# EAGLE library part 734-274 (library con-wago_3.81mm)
Serie 734, Stiftleiste (für Leiterplatten) Einlötstift abgewinkelt 1 x 1 mm / Series 734, Male header (for PCBs) Angled solder pin 1 x 1 mm Polzahl / Pole No.: 14 Rastermaß / Pitch: 3.81 mm Bemessungsspannung / Rated Voltage: 160 V Nennstrom / Nominal Current: 10 A Lötstiftlänge: / Solder Pin Length: 3.8 mm Farbe / Color: orange / orange Stand: 01.01.2012. Die jeweils aktuellen Daten zu diesem Artikel finden Sie in unserem Produktkatalog, den Sie unter www.wago.com einsehen können. As of: 01/01/2012. Please find the newest data for this article in our product catalogue, which can be viewed under www.wago.com.
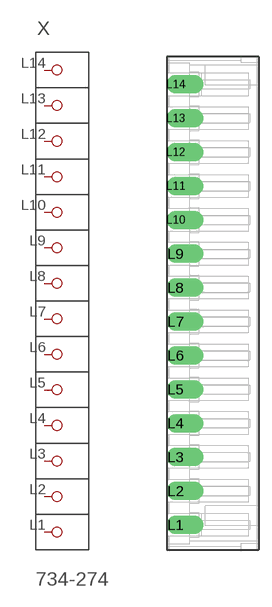
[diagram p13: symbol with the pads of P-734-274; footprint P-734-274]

Designator prefix X

## 734-274  [P-734-274]
L1  P1
L2  P2
L3  P3
L4  P4
L5  P5
L6  P6
L7  P7
L8  P8
L9  P9
L10  P10
L11  P11
L12  P12
L13  P13
L14  P14

## Footprint P-734-274 (pad centres in mm)
drill 1.4 pad 2 offset: L1 -4.15,-24.915; L2 -4.15,-21.105; L3 -4.15,-17.295; L4 -4.15,-13.485; L5 -4.15,-9.675; L6 -4.15,-5.865; L7 -4.15,-2.055; L8 -4.15,1.755; L9 -4.15,5.565; L10 -4.15,9.375; L11 -4.15,13.185; L12 -4.15,16.995; L13 -4.15,20.805; L14 -4.15,24.615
